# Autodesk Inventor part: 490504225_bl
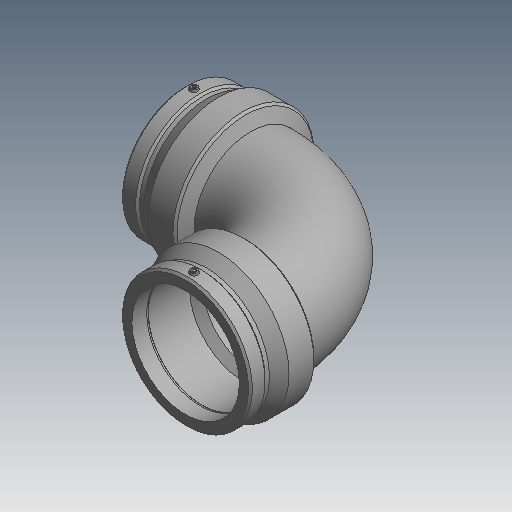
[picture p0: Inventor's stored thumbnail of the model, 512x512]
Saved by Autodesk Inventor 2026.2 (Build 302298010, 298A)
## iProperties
Created: 2017-06
Part Number: 490504225_bl
Material: Generic
Description: PLASSON 90° ELBOW 225
Document SubType Name: Modeling
Designer: KIM
Mass: 55.0731 g
Surface Area: 148.067 cm^2
Volume: 55.0731 cm^3
Density: 1 g/cm^3
Appearance: Default
Author: KIM
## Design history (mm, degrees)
derived "490504.ipt"
feature "Solid1::490504.ipt" dims "ScaleForDerivedMember" = 10
tag "TaggingFeature1"
body "Solid1"
other parameters: "d2" = 295 [user parameter], "d4" = 124.5 [user parameter], "d5" = 265.5 [user parameter], "d8" = 168 deg [user parameter], "d10" = 48.4 [user parameter], "d11" = 16.13333 [user parameter], "d14" = 17.6296 [user parameter], "d18" = 225 [user parameter], "d19" = 3.52592 [user parameter], "d20" = 168 deg [user parameter], "d22" = 271.4 [user parameter], "d23" = 295 [user parameter], "d24" = 263.258 [user parameter], "d30" = 15 [user parameter], "d31" = 174.3 [user parameter], "d34" = 5 deg [user parameter], "d35" = 15 [user parameter], "d39" = 5 deg [user parameter], "d41" = 4 [user parameter], "d42" = 14 [user parameter], "d43" = 0 [user parameter], "d45" = 4 [user parameter], "d46" = 14 [user parameter], "d47" = 0 [user parameter], "d49" = 225 [user parameter], "d50" = 191.25 [user parameter], "d51" = 48.4 [user parameter], "d52" = 121 [user parameter], "d54" = 90 deg [user parameter], "d65" = 225 [user parameter], "d67" = 45 deg [user parameter], "d71" = 90 deg [user parameter], "d75" = 14.75 [user parameter], "d82" = 45 deg [user parameter], "d83" = 121 [user parameter], "d84" = 265.5 [user parameter], "d87" = 90 deg [user parameter], "d90" = 121 [user parameter], "d91" = 0 [user parameter], "d92" = 121 [user parameter], "d93" = 0 [user parameter], "d94" = 90 deg [user parameter], "d101" = 3 [user parameter], "d102" = 0 [user parameter], "d103" = 3 [user parameter], "d104" = 0 [user parameter], "d105" = 35.09 [user parameter], "d106" = 8.7725 [user parameter], "d110" = 66.55 [user parameter], "d111" = 498 [user parameter], "d112" = 498 [user parameter], "d113" = 498 [user parameter], "d114" = 498 [user parameter], "d_" = 225 [user parameter], "L_" = 498 [user parameter], "L_1" = 121 [user parameter], "D_" = 295 [user parameter], "d_2" = 12 [user parameter]
